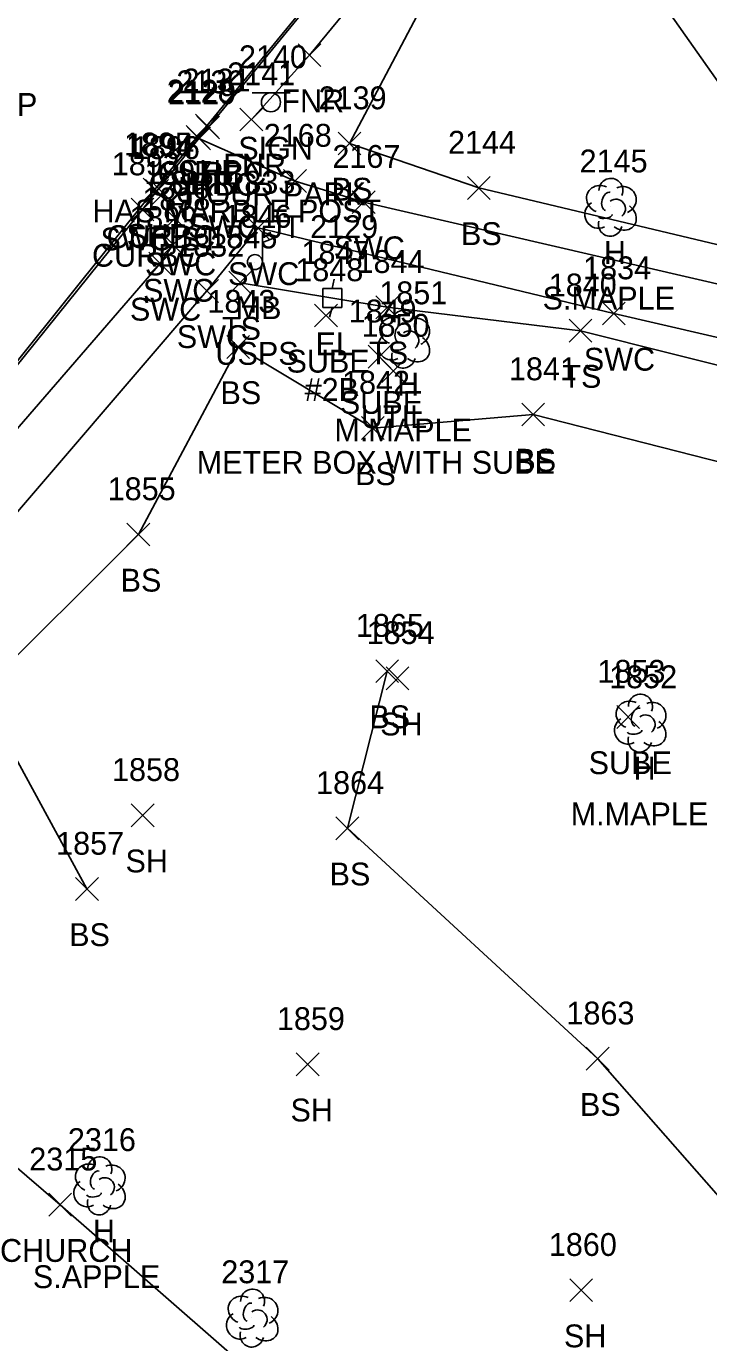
# Model space of a CAD drawing. Extents: x 1462668 to 1465147, y 550359 to 557351.
# Drawn here: x 1464791.7 to 1464851.4, y 552631.2 to 552746.4 of the extents above; entities that cross this region are included whole.
import ezdxf

# ---------------------------------------------------------------- set-up
doc = ezdxf.new("R2010")
doc.units = 0
for name, color, linetype in [('L_A', 7, 'Continuous'), ('L_C', 7, 'Continuous'), ('L_I', 7, 'Continuous'), ('L_TIC', 7, 'Continuous'), ('LBC', 7, 'Continuous'), ('LELB', 7, 'Continuous'), ('LFNC', 7, 'Continuous'), ('LMB', 7, 'Continuous'), ('LTD', 7, 'Continuous'), ('P_A', 7, 'Continuous'), ('P_I', 7, 'Continuous'), ('P_TIC', 7, 'Continuous'), ('PSP', 7, 'Continuous'), ('R_A', 7, 'Continuous'), ('R_I', 7, 'Continuous'), ('R_TIC', 7, 'Continuous'), ('RC', 7, 'Continuous'), ('RSW', 7, 'Continuous'), ('S_A', 7, 'Continuous'), ('S_C', 7, 'Continuous'), ('S_I', 7, 'Continuous'), ('SSGN', 7, 'Continuous'), ('U_A', 7, 'Continuous'), ('U_C', 7, 'Continuous'), ('U_I', 7, 'Continuous'), ('U_TIC', 7, 'Continuous'), ('UDEFAULT', 7, 'Continuous'), ('UEPT', 7, 'Continuous')]:
    doc.layers.add(name, color=color, linetype=linetype)

msp = doc.modelspace()

# ---------------------------------------------------------------- linework, layer by layer
at = {"layer": 'L_TIC'}
for points in [[(1464815.49, 552742.87), (1464817.49, 552744.87)], [(1464817.49, 552742.87), (1464815.49, 552744.87)], [(1464810.41, 552737.23), (1464812.41, 552739.23)], [(1464812.41, 552737.23), (1464810.41, 552739.23)], [(1464818.99, 552735.13), (1464820.99, 552737.13)], [(1464820.99, 552735.13), (1464818.99, 552737.13)], [(1464830.31, 552731.24), (1464832.31, 552733.24)], [(1464832.31, 552731.24), (1464830.31, 552733.24)], [(1464809.42, 552722.95), (1464811.42, 552724.95)], [(1464811.42, 552722.95), (1464809.42, 552724.95)], [(1464822.3, 552720.8), (1464824.3, 552722.8)], [(1464824.3, 552720.8), (1464822.3, 552722.8)], [(1464839.21, 552718.75), (1464841.21, 552720.75)], [(1464841.21, 552718.75), (1464839.21, 552720.75)], [(1464809.25, 552717.32), (1464811.25, 552719.32)], [(1464811.25, 552717.32), (1464809.25, 552719.32)], [(1464835.07, 552711.41), (1464837.07, 552713.41)], [(1464837.07, 552711.41), (1464835.07, 552713.41)], [(1464821.03, 552710.23), (1464823.03, 552712.23)], [(1464823.03, 552710.23), (1464821.03, 552712.23)], [(1464800.52, 552700.91), (1464802.52, 552702.91)], [(1464802.52, 552700.91), (1464800.52, 552702.91)], [(1464822.29, 552688.95), (1464824.29, 552690.95)], [(1464824.29, 552688.95), (1464822.29, 552690.95)], [(1464823.2, 552688.32), (1464825.2, 552690.32)], [(1464825.2, 552688.32), (1464823.2, 552690.32)], [(1464800.9, 552676.33), (1464802.9, 552678.33)], [(1464802.9, 552676.33), (1464800.9, 552678.33)], [(1464818.81, 552675.19), (1464820.81, 552677.19)], [(1464820.81, 552675.19), (1464818.81, 552677.19)], [(1464796.02, 552669.88), (1464798.02, 552671.88)], [(1464798.02, 552669.88), (1464796.02, 552671.88)], [(1464815.34, 552654.53), (1464817.34, 552656.53)], [(1464817.34, 552654.53), (1464815.34, 552656.53)], [(1464840.72, 552655.02), (1464842.72, 552657.02)], [(1464842.72, 552655.02), (1464840.72, 552657.02)], [(1464793.67, 552642.24), (1464795.67, 552644.24)], [(1464795.67, 552642.24), (1464793.67, 552644.24)], [(1464839.27, 552634.76), (1464841.27, 552636.76)], [(1464841.27, 552634.76), (1464839.27, 552636.76)]]:
    msp.add_lwpolyline(points, dxfattribs=at)
at = {"layer": 'LBC'}
msp.add_lwpolyline([(1464741.39, 552619.99), (1464753.12, 552633.72), (1464750.2, 552636.25), (1464760.72, 552648.59), (1464763.84, 552646.09), (1464775.47, 552659.71), (1464794.67, 552643.24), (1464814.32, 552626.05)], dxfattribs=at)
at = {"layer": 'LELB'}
for points in [[(1464875.43, 552806.2), (1464863.86, 552787.59), (1464848.84, 552770.46), (1464840.99, 552757.52), (1464853.62, 552739.59), (1464872.44, 552745.15)], [(1464828.56, 552752.39), (1464819.99, 552736.13), (1464831.31, 552732.24), (1464867.47, 552723.66), (1464878.19, 552720.93), (1464883.47, 552728.79), (1464898.85, 552749.23), (1464914.9, 552763.87)], [(1464883.33, 552709.65), (1464865.1, 552713.49), (1464840.21, 552719.75), (1464823.3, 552721.8), (1464810.42, 552723.95)], [(1464879.78, 552700.74), (1464862.7, 552705.61), (1464836.07, 552712.41), (1464822.03, 552711.23), (1464810.25, 552718.32), (1464801.52, 552701.91), (1464787.63, 552688.07), (1464797.02, 552670.88)], [(1464856, 552622.19), (1464855.47, 552640.37), (1464841.72, 552656.02), (1464819.81, 552676.19), (1464823.29, 552689.95)]]:
    msp.add_lwpolyline(points, dxfattribs=at)
at = {"layer": 'LFNC'}
msp.add_lwpolyline([(1464811.41, 552738.23), (1464816.49, 552743.87), (1464822.82, 552751.58)], dxfattribs=at)
at = {"layer": 'LMB'}
for p, q in [((1464812.37, 552728.36), (1464813.67, 552727.98)), ((1464812.38, 552725.77), (1464812.38, 552728.36)), ((1464812.38, 552727.46), (1464813.66, 552727.97)), ((1464811.72, 552725.76), (1464811.72, 552725.76))]:
    msp.add_line(p, q, dxfattribs=at)
msp.add_circle((1464811.72, 552725.76), 0.656, dxfattribs=at)
at = {"layer": 'LTD'}
for p, q in [((1464842.82, 552730.6), (1464842.82, 552730.6)), ((1464842.82, 552730.6), (1464842.82, 552730.6)), ((1464824.73, 552719.06), (1464824.73, 552719.06)), ((1464824.73, 552719.06), (1464824.73, 552719.06)), ((1464845.41, 552685.45), (1464845.41, 552685.45)), ((1464845.41, 552685.45), (1464845.41, 552685.45)), ((1464798.09, 552644.94), (1464798.09, 552644.94)), ((1464798.09, 552644.94), (1464798.09, 552644.94)), ((1464811.46, 552633.37), (1464811.46, 552633.37)), ((1464811.46, 552633.37), (1464811.46, 552633.37))]:
    msp.add_line(p, q, dxfattribs=at)
for centre in [(1464842.87, 552732.03), (1464824.78, 552720.5), (1464845.46, 552686.88), (1464798.14, 552646.38), (1464811.51, 552634.8)]:
    msp.add_arc(centre, 1.05, 335.5272, 180.9563, dxfattribs=at)
for centre, major_axis, ratio, start_param, end_param in [((1464842.03, 552731.26), (1.21, -0.51), 0.895232, 1.570796, 4.712389), ((1464843.86, 552731.18), (-1.14, -0.48), 0.949671, 1.570796, 4.712389), ((1464842.61, 552731.06), (-0.208, -0.792), 0.645439, 3.141593, 6.283185), ((1464843.32, 552730.43), (-0.5, 0.667), 0.989748, 3.141593, 6.283185), ((1464841.74, 552729.89), (0.58, -1.04), 0.959034, 3.141593, 6.283185), ((1464843.82, 552729.76), (-1.09, 0.79), 0.841452, 1.570796, 4.712389), ((1464842.82, 552729.1), (0.26, 1.06), 0.942809, 1.570796, 4.712389), ((1464842.37, 552729.85), (-0.625, -0.083), 0.423636, 0, 3.141593), ((1464823.94, 552719.73), (1.21, -0.51), 0.895232, 1.570796, 4.712389), ((1464825.77, 552719.65), (-1.14, -0.48), 0.949671, 1.570796, 4.712389), ((1464824.52, 552719.52), (-0.208, -0.792), 0.645439, 3.141593, 6.283185), ((1464825.23, 552718.9), (-0.5, 0.667), 0.989748, 3.141593, 6.283185), ((1464823.65, 552718.35), (0.58, -1.04), 0.959034, 3.141593, 6.283185), ((1464825.73, 552718.23), (-1.09, 0.79), 0.841452, 1.570796, 4.712389), ((1464824.73, 552717.56), (0.26, 1.06), 0.942809, 1.570796, 4.712389), ((1464824.27, 552718.31), (-0.625, -0.083), 0.423636, 0, 3.141593), ((1464844.62, 552686.12), (1.21, -0.51), 0.895232, 1.570796, 4.712389), ((1464845.21, 552685.91), (-0.208, -0.792), 0.645439, 3.141593, 6.283185), ((1464846.46, 552686.03), (-1.14, -0.48), 0.949671, 1.570796, 4.712389), ((1464844.33, 552684.74), (0.58, -1.04), 0.959034, 3.141593, 6.283185), ((1464845.91, 552685.28), (-0.5, 0.667), 0.989748, 3.141593, 6.283185), ((1464846.41, 552684.62), (-1.09, 0.79), 0.841452, 1.570796, 4.712389), ((1464845.41, 552683.95), (0.26, 1.06), 0.942809, 1.570796, 4.712389), ((1464844.96, 552684.7), (-0.625, -0.083), 0.423636, 0, 3.141593), ((1464797.3, 552645.61), (1.21, -0.51), 0.895232, 1.570796, 4.712389), ((1464797.88, 552645.4), (-0.208, -0.792), 0.645439, 3.141593, 6.283185), ((1464799.13, 552645.53), (-1.14, -0.48), 0.949671, 1.570796, 4.712389), ((1464797.01, 552644.24), (0.58, -1.04), 0.959034, 3.141593, 6.283185), ((1464798.59, 552644.78), (-0.5, 0.667), 0.989748, 3.141593, 6.283185), ((1464799.09, 552644.11), (-1.09, 0.79), 0.841452, 1.570796, 4.712389), ((1464798.09, 552643.44), (0.26, 1.06), 0.942809, 1.570796, 4.712389), ((1464797.64, 552644.19), (-0.625, -0.083), 0.423636, 0, 3.141593), ((1464810.67, 552634.04), (1.21, -0.51), 0.895232, 1.570796, 4.712389), ((1464811.25, 552633.83), (-0.208, -0.792), 0.645439, 3.141593, 6.283185), ((1464812.5, 552633.95), (-1.14, -0.48), 0.949671, 1.570796, 4.712389), ((1464810.38, 552632.66), (0.58, -1.04), 0.959034, 3.141593, 6.283185), ((1464811.96, 552633.2), (-0.5, 0.667), 0.989748, 3.141593, 6.283185), ((1464812.46, 552632.54), (-1.09, 0.79), 0.841452, 1.570796, 4.712389), ((1464811.46, 552631.87), (0.26, 1.06), 0.942809, 1.570796, 4.712389), ((1464811, 552632.62), (-0.625, -0.083), 0.423636, 0, 3.141593)]:
    msp.add_ellipse(centre, major_axis=major_axis, ratio=ratio, start_param=start_param, end_param=end_param, dxfattribs=at)
at = {"layer": 'P_TIC'}
for points in [[(1464806.51, 552736.69), (1464808.51, 552738.69)], [(1464808.51, 552736.69), (1464806.51, 552738.69)], [(1464805.7, 552735.72), (1464807.7, 552737.72)], [(1464807.7, 552735.72), (1464805.7, 552737.72)], [(1464801.94, 552731.09), (1464803.94, 552733.09)], [(1464803.94, 552731.09), (1464801.94, 552733.09)]]:
    msp.add_lwpolyline(points, dxfattribs=at)
at = {"layer": 'PSP'}
msp.add_lwpolyline([(1464713.64, 552621.47), (1464720.3, 552630.09), (1464743.11, 552657.96), (1464771.73, 552693.19), (1464802.94, 552732.09), (1464806.7, 552736.72), (1464807.51, 552737.69), (1464827.96, 552762.61), (1464840.31, 552778.01), (1464860.3, 552803.04), (1464847.06, 552806.2), (1464846.96, 552807.41), (1464865.09, 552816), (1464884.93, 552820.04), (1464894.44, 552821.2), (1464905.2, 552819.49), (1464914.43, 552816.32), (1464923.05, 552811.38)], dxfattribs=at)
at = {"layer": 'R_TIC'}
for points in [[(1464806.62, 552736.53), (1464808.62, 552738.53)], [(1464808.62, 552736.53), (1464806.62, 552738.53)], [(1464805.82, 552735.57), (1464807.82, 552737.57)], [(1464807.82, 552735.57), (1464805.82, 552737.57)], [(1464814.23, 552731.85), (1464816.23, 552733.85)], [(1464816.23, 552731.85), (1464814.23, 552733.85)], [(1464802.14, 552730.98), (1464804.14, 552732.98)], [(1464804.14, 552730.98), (1464802.14, 552732.98)], [(1464802.7, 552730.77), (1464804.7, 552732.77)], [(1464804.7, 552730.77), (1464802.7, 552732.77)], [(1464800.88, 552729.35), (1464802.88, 552731.35)], [(1464802.88, 552729.35), (1464800.88, 552731.35)], [(1464820.24, 552730), (1464822.24, 552732)], [(1464822.24, 552730), (1464820.24, 552732)], [(1464803.73, 552728.59), (1464805.73, 552730.59)], [(1464805.73, 552728.59), (1464803.73, 552730.59)], [(1464810.99, 552727.74), (1464812.99, 552729.74)], [(1464812.99, 552727.74), (1464810.99, 552729.74)], [(1464803.56, 552726.28), (1464805.56, 552728.28)], [(1464805.56, 552726.28), (1464803.56, 552728.28)], [(1464802.42, 552724.63), (1464804.42, 552726.63)], [(1464804.42, 552724.63), (1464802.42, 552726.63)], [(1464806.52, 552722.23), (1464808.52, 552724.23)], [(1464808.52, 552722.23), (1464806.52, 552724.23)], [(1464842.13, 552720.25), (1464844.13, 552722.25)], [(1464844.13, 552720.25), (1464842.13, 552722.25)]]:
    msp.add_lwpolyline(points, dxfattribs=at)
at = {"layer": 'RC'}
msp.add_lwpolyline([(1464714.1, 552621.11), (1464713.72, 552621.38), (1464720.51, 552629.87), (1464743.2, 552657.68), (1464745.71, 552660.87), (1464771.87, 552693.09), (1464801.88, 552730.35), (1464803.14, 552731.98), (1464806.82, 552736.57), (1464807.62, 552737.53), (1464827.98, 552762.36), (1464840.55, 552777.99), (1464860.73, 552803.16), (1464848.01, 552806.27), (1464847.4, 552807.43), (1464865.21, 552815.86), (1464884.88, 552819.62), (1464894.44, 552820.83), (1464904.96, 552819.1), (1464914.17, 552815.93), (1464922.75, 552811.24)], dxfattribs=at)
at = {"layer": 'RSW'}
for points in [[(1464815.23, 552732.85), (1464806.82, 552736.57)], [(1464883.57, 552716.47), (1464857.95, 552722.51), (1464821.24, 552731), (1464815.23, 552732.85)], [(1464803.7, 552731.77), (1464804.73, 552729.59), (1464804.56, 552727.28), (1464803.42, 552725.63), (1464787.33, 552707.03), (1464764.32, 552680.71), (1464746.63, 552660.43)], [(1464757.36, 552645.64), (1464754.47, 552647.95), (1464747.39, 552654.01), (1464767.97, 552677.6), (1464784.12, 552696.11), (1464787.62, 552700.03), (1464807.52, 552723.23), (1464811.99, 552728.74), (1464843.13, 552721.25), (1464884.11, 552711.76)]]:
    msp.add_lwpolyline(points, dxfattribs=at)
at = {"layer": 'SSGN'}
for p, q in [((1464811.48, 552740.58), (1464814.81, 552740.58)), ((1464813.12, 552739.74), (1464813.12, 552739.74))]:
    msp.add_line(p, q, dxfattribs=at)
msp.add_circle((1464813.12, 552739.74), 0.833, dxfattribs=at)
at = {"layer": 'U_TIC'}
for points in [[(1464816.94, 552720.08), (1464818.94, 552722.08)], [(1464818.94, 552720.08), (1464816.94, 552722.08)], [(1464821.62, 552716.47), (1464823.62, 552718.47)], [(1464823.62, 552716.47), (1464821.62, 552718.47)], [(1464843.38, 552684.93), (1464845.38, 552686.93)], [(1464845.38, 552684.93), (1464843.38, 552686.93)]]:
    msp.add_lwpolyline(points, dxfattribs=at)
at = {"layer": 'UDEFAULT'}
for points in [[(1464822.83, 552715.22), (1464824.83, 552717.22)], [(1464824.83, 552715.22), (1464822.83, 552717.22)]]:
    msp.add_lwpolyline(points, dxfattribs=at)
at = {"layer": 'UEPT'}
for p, q in [((1464818.65, 552724.27), (1464818.48, 552723.44)), ((1464817.65, 552721.77), (1464817.65, 552723.44)), ((1464817.65, 552723.44), (1464819.32, 552723.44)), ((1464819.32, 552723.44), (1464819.32, 552721.77)), ((1464818.48, 552722.6), (1464818.48, 552722.6)), ((1464819.32, 552721.77), (1464817.65, 552721.77)), ((1464818.23, 552720.94), (1464818.48, 552721.77))]:
    msp.add_line(p, q, dxfattribs=at)

# ---------------------------------------------------------------- texts
at = {"layer": 'L_A'}
for s, p in [('FNR', (1464814.03, 552738.87)), ('FNR', (1464808.95, 552733.23)), ('BS', (1464818.43, 552731.13)), ('BS', (1464829.75, 552727.24)), ('H', (1464842.26, 552725.6)), ('MB', (1464810.03, 552720.76)), ('TS', (1464808.83, 552718.95)), ('TS', (1464821.71, 552716.8)), ('TS', (1464838.62, 552714.75)), ('BS', (1464808.7, 552713.32)), ('H', (1464824.16, 552714.06)), ('BS', (1464834.51, 552707.41)), ('BS', (1464820.48, 552706.23)), ('BS', (1464799.96, 552696.91)), ('BS', (1464821.73, 552684.95)), ('SH', (1464822.68, 552684.32)), ('H', (1464844.85, 552680.45)), ('SH', (1464800.39, 552672.33)), ('BS', (1464818.25, 552671.19)), ('BS', (1464795.46, 552665.88)), ('BS', (1464840.16, 552651.02)), ('SH', (1464814.83, 552650.53)), ('H', (1464797.53, 552639.94)), ('CHURCH', (1464789.41, 552638.24)), ('SH', (1464838.76, 552630.76))]:
    msp.add_text(s, height=2, dxfattribs=at).set_placement(p)
at = {"layer": 'L_C'}
for s, p in [('HAS MARBLE POST', (1464797.5, 552729.23)), ('S.MAPLE', (1464836.89, 552721.6)), ('USPS', (1464808.26, 552716.76)), ('M.MAPLE', (1464818.67, 552710.06)), ('M.MAPLE', (1464839.35, 552676.45)), ('S.APPLE', (1464792.28, 552635.94))]:
    msp.add_text(s, height=2, dxfattribs=at).set_placement(p)
at = {"layer": 'L_I'}
for s, p in [('2141', (1464809.29, 552741.23)), ('2139', (1464817.29, 552739.13)), ('2144', (1464828.62, 552735.24)), ('2145', (1464840.13, 552733.6)), ('1846', (1464808.97, 552728.76)), ('1845', (1464807.73, 552726.95)), ('1844', (1464820.61, 552724.8)), ('1840', (1464837.43, 552722.75)), ('1843', (1464807.56, 552721.32)), ('1851', (1464822.6, 552722.06)), ('1841', (1464833.95, 552715.41)), ('1842', (1464819.34, 552714.23)), ('1855', (1464798.83, 552704.91)), ('1865', (1464820.55, 552692.95)), ('1854', (1464821.5, 552692.32)), ('1852', (1464842.72, 552688.45)), ('1858', (1464799.21, 552680.33)), ('1864', (1464817.07, 552679.19)), ('1857', (1464794.32, 552673.88)), ('1863', (1464838.98, 552659.02)), ('1859', (1464813.64, 552658.53)), ('2316', (1464795.35, 552647.94)), ('2315', (1464791.97, 552646.24)), ('1860', (1464837.44, 552638.76)), ('2317', (1464808.77, 552636.37))]:
    msp.add_text(s, height=2, dxfattribs=at).set_placement(p)
at = {"layer": 'P_A'}
for s, p in [('RDP', (1464787.03, 552738.55)), ('SHP', (1464805.05, 552732.69)), ('SHP', (1464804.23, 552731.72)), ('SHP', (1464800.48, 552727.09))]:
    msp.add_text(s, height=2, dxfattribs=at).set_placement(p)
at = {"layer": 'P_I'}
for s, p in [('2131', (1464805.39, 552740.69)), ('2128', (1464804, 552739.72)), ('1895', (1464800.25, 552735.09))]:
    msp.add_text(s, height=2, dxfattribs=at).set_placement(p)
at = {"layer": 'R_A'}
for s, p in [('CURBC', (1464802.4, 552731.57)), ('CURBC', (1464803.2, 552732.53)), ('CURBC', (1464798.73, 552726.98)), ('SWC JT 2129', (1464805.85, 552727.85)), ('SWC ST', (1464798.2, 552726.77)), ('SWC', (1464818.6, 552726)), ('CURBC', (1464797.46, 552725.35)), ('SWC', (1464802.09, 552724.59)), ('SWC', (1464809.36, 552723.74)), ('SWC', (1464801.92, 552722.28)), ('SWC', (1464800.78, 552720.63)), ('SWC', (1464804.88, 552718.23)), ('SWC', (1464840.5, 552716.25))]:
    msp.add_text(s, height=2, dxfattribs=at).set_placement(p)
at = {"layer": 'R_I'}
for s, p in [('2129', (1464804.12, 552739.57)), ('2130', (1464804.84, 552740.53)), ('1894', (1464800.45, 552734.98)), ('2168', (1464812.49, 552735.85)), ('1896', (1464800.95, 552734.77)), ('2167', (1464818.5, 552734)), ('1893', (1464799.19, 552733.35)), ('1897', (1464802.03, 552732.59)), ('1833', (1464809.3, 552731.74)), ('1898', (1464801.86, 552730.28)), ('1899', (1464800.72, 552728.63)), ('1832', (1464804.83, 552726.23)), ('1834', (1464840.44, 552724.25))]:
    msp.add_text(s, height=2, dxfattribs=at).set_placement(p)
at = {"layer": 'S_A'}
msp.add_text('SIGN', height=2, dxfattribs=at).set_placement((1464810.26, 552734.72))
at = {"layer": 'S_C'}
msp.add_text('2HOUR PARK', height=2, dxfattribs=at).set_placement((1464804.05, 552730.72))
at = {"layer": 'S_I'}
msp.add_text('2140', height=2, dxfattribs=at).set_placement((1464810.32, 552742.72))
at = {"layer": 'U_A'}
for s, p in [('EL', (1464817.02, 552717.6)), ('SUBE', (1464814.48, 552716.08)), ('SUBE', (1464819.15, 552712.47)), ('UTIL', (1464820.99, 552711.22)), ('SUBE', (1464840.92, 552680.93))]:
    msp.add_text(s, height=2, dxfattribs=at).set_placement(p)
at = {"layer": 'U_C'}
for s, p in [('#2B', (1464816.07, 552713.6)), ('METER BOX WITH SUBE', (1464806.62, 552707.22))]:
    msp.add_text(s, height=2, dxfattribs=at).set_placement(p)
at = {"layer": 'U_I'}
for s, p in [('1847', (1464815.79, 552725.6)), ('1848', (1464815.25, 552724.08)), ('1849', (1464819.92, 552720.47)), ('1850', (1464821.05, 552719.22)), ('1853', (1464841.69, 552688.93))]:
    msp.add_text(s, height=2, dxfattribs=at).set_placement(p)

doc.saveas('drawing.dxf')
